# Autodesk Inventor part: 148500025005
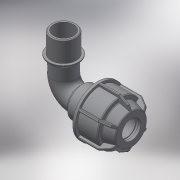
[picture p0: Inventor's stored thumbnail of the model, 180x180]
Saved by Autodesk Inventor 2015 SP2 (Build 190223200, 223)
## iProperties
Created: 2017-08
Part Number: 148500025005
Material: Generic
Description: PLASSON L.14 90° ELBOW MALE ADAPTOR (SILVER) 25-1/2"
Document SubType Name: Modeling
Designer: KIM
Density: 1 g/cm^3
Appearance: Default
Author: KIM
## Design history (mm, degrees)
derived "148500.ipt"
feature "Solid1::148500.ipt"
feature "Solid2::148500.ipt"
tag "TaggingFeature1"
body "Solid1"
body "Solid2"
other parameters: "d1" = 25, "d2" = 47, "d4" = 15 deg, "d5" = 31.02, "d6" = 10.2366, "d16" = 25.5, "d17" = 2.35, "d24" = 2.35, "d25" = 45, "d26" = 37.5, "d27" = 2.35, "d28" = 135 deg, "d29" = 1.41, "d31" = 1.25, "d46" = 150 deg, "d49" = 2.5, "d50" = 0, "d58" = 0.75, "d61" = 360 deg, "d63" = 17.5, "d94" = 45, "d96" = 23.0505, "d97" = 17, "d98" = 16.764, "d99" = 19.59292, "d100" = 135 deg, "d108" = 1.25, "d112" = 22.1, "d113" = 62, "d114" = 51.7, "d115" = 19.59292, "d116" = 45 deg, "d117" = 0, "d118" = 0, "d119" = 20.955, "d120" = 17, "d121" = 25.146, "d122" = 17.85, "d123" = 1, "d_" = 25, "R_" = 20.955, "A_" = 62, "l_" = 47, "l_2" = 17, "A_1" = 45
